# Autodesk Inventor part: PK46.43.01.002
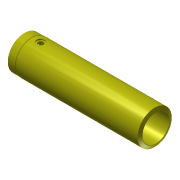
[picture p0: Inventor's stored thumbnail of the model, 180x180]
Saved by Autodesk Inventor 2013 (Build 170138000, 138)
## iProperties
Shininess: 64.0
Length Units: 11269
Angle Units: 11279
Time Units: 11290
Mass Units: 11283
Length Display Precision: 3
Angle Display Precision: 2
Compacted: True
Part Number: PK46.43.01.002
Document SubType Name: Modeling
Created: 2004-11
Material: Сталь высокопрочная низколегированная
Designer: ELarisa
Manufacturer: Standard
Standards Organization: Custom
Density: 7.84 g/cm^3
Density: 0.0
Volumn: 0.0
Area: 0.0
PropertySet Name: Model Information
Control State: 0
Master: False
Checked Out: False
Checked Out Date: 2008-10-15
Last Check In Date: 2008-10-15
Author: ELarisa
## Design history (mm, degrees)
revolve "Вращение1" stored, may be unused: angle "d10" = 90 deg
node "РабОсь1"
node "РабПлоскость1"
sketch "Эскиз2"
  geometry: L1 (-98, 0)-(588, 0) reference; L2 (0, -60.5)-(0, 60.5) reference; 1 further point
  dimensions: "d15" = 0 distance from line of L1 point (62, 0); "d35" = 62 distance from line of point (62, 0) L2
hole "Отверстие1" sketch "Эскиз2" diameter "d16" = 20; stored, may be unused: countersink angle "d20" = 82 deg, drill point angle "d22" = 118 deg; dims "d17" = 6, "d18" = 30, "d19" = 5, "d21" = 15
body "Solid1"
sketch "Эскиз1"
  geometry: L1 (0, 0)-(0, 60.5); L2 (35, 63.5)-(485.45, 63.5); L3 (485.45, 63.5)-(490, 51); L4 (490, 51)-(490, 0); L5 (490, 0)-(0, 0); L6 (490, 50)-(10.5, 50); L7 (35, 61)-(30, 61); L8 (30, 61)-(28.5, 62.5); L9 (28.5, 62.5)-(2, 62.5); L10 (35, 61)-(35, 63.5); L11 (10.5, 50)-(5.5, 51.34); L12 (5.5, 51.34)-(5.5, 55); L13 (5.5, 55)-(0, 55); L14 (2, 62.5)-(0, 60.5)
  constraints: 28 end point, 4 parallel, 3 perpendicular, 2 point on line, 1 vertical, 1 other
  dimensions: "d0" = 490 distance of L4.end L1.start; "d2" = 20 deg angle of L4 L3; "d3" = 63.5 distance between parallel lines of L2 L5; "d4" = 51 distance of L3.end L4.end; "d7" = 50 distance between parallel lines of L5 L6; "d24" = 15 deg angle of L6 L11; "d25" = 2 horizontal distance of L9.end L1.end; "d26" = 135 deg angle of L9 L14; "d27" = 5.5 distance of L12.end L13.end; "d28" = 5 horizontal distance of L6.end L11.end; "d29" = 55 distance between parallel lines of L5 L13; "d30" = 62.5 distance between parallel lines of L5 L9; "d31" = 135 deg angle of L8 L9; "d32" = 5 distance of L7.start L7.end; "d33" = 61 distance between parallel lines of L5 L7; "d34" = 35 distance from line of L2.start L1
other parameters: "d13" = 63.5
